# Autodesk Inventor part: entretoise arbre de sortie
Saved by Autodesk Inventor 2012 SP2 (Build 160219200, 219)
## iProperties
Created: 2013-04
Part Number: entretoise arbre de sortie
Material: Default
Document SubType Name: Modeling
Designer: papa
Density: 1 g/cm^3
Mass: 3.25775 g
Surface Area: 30.5763 cm^2
Volume: 3.25775 cm^3
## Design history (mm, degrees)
node "entretoise arbre de sortie1"
node "entretoise arbre de sortie"
node "Base1"
